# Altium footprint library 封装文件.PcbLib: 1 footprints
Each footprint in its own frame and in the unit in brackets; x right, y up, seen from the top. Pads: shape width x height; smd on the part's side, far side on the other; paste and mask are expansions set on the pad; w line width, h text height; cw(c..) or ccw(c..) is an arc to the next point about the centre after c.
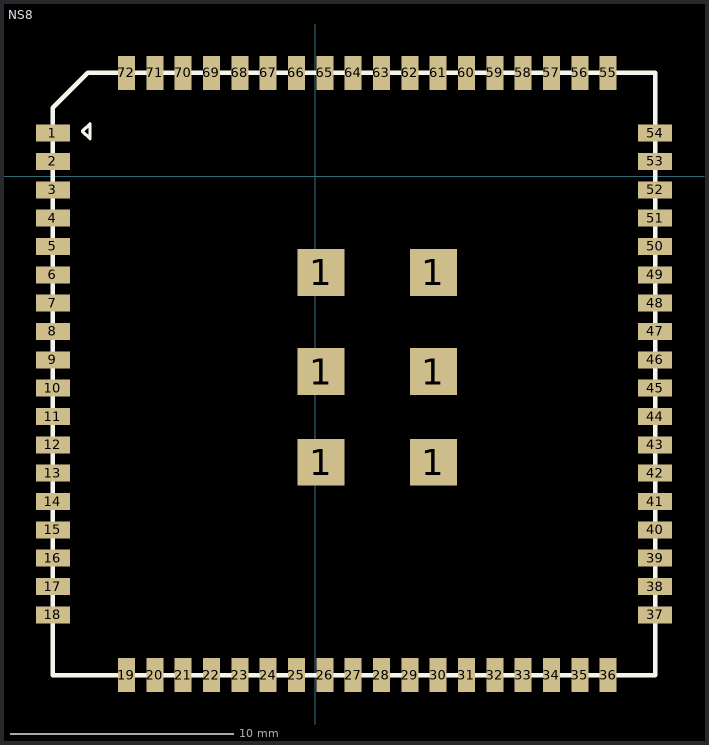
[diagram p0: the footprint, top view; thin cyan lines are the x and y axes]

## NS8 [mil]
pads (78):
  rect 60x30 smd: 1(-463.27,75.98) 2(-463.27,25.98) 3(-463.27,-24.02) 4(-463.27,-74.02) 5(-463.27,-124.02) 6(-463.27,-174.02) 7(-463.27,-224.02) 8(-463.27,-274.02) 9(-463.27,-324.02) 10(-463.27,-374.02) 11(-463.27,-424.02) 12(-463.27,-474.02) 13(-463.27,-524.02) 14(-463.27,-574.02) 15(-463.27,-624.02) 16(-463.27,-674.02) 17(-463.27,-724.02) 18(-463.27,-774.02) 37(599.72,-774.02) 38(599.72,-724.02) 39(599.72,-674.02) 40(599.72,-624.02) 41(599.72,-574.02) 42(599.72,-524.02) 43(599.72,-474.02) 44(599.72,-424.02) 45(599.72,-374.02) 46(599.72,-324.02) 47(599.72,-274.02) 48(599.72,-224.02) 49(599.72,-174.02) 50(599.72,-124.02) 51(599.72,-74.02) 52(599.72,-24.02) 53(599.72,25.98) 54(599.72,75.98)
  rect 82.68x82.68 smd: 1(10.17,-504.69) 1(10.17,-344.69) 1(10.17,-169.69) 1(208.32,-504.69) 1(208.32,-344.69) 1(208.32,-169.69)
  rect 30x60 smd: 19(-333.35,-880.51) 20(-283.35,-880.51) 21(-233.35,-880.51) 22(-183.35,-880.51) 23(-133.35,-880.51) 24(-83.35,-880.51) 25(-33.35,-880.51) 26(16.65,-880.51) 27(66.65,-880.51) 28(116.65,-880.51) 29(166.65,-880.51) 30(216.65,-880.51) 31(266.65,-880.51) 32(316.65,-880.51) 33(366.65,-880.51) 34(416.65,-880.51) 35(466.65,-880.51) 36(516.65,-880.51) 55(516.65,182.48) 56(466.65,182.48) 57(416.65,182.48) 58(366.65,182.48) 59(316.65,182.48) 60(266.65,182.48) 61(216.65,182.48) 62(166.65,182.48) 63(116.65,182.48) 64(66.65,182.48) 65(16.65,182.48) 66(-33.35,182.48) 67(-83.35,182.48) 68(-133.35,182.48) 69(-183.35,182.48) 70(-233.35,182.48) 71(-283.35,182.48) 72(-333.35,182.48)
Top Overlay:
  lines w3.94: -410.91,79.33 -410.91,79.33
  lines w5.91: -410.91,79.33 -397.52,65.94 -397.52,92.72 -410.91,79.33
  lines w7.87: -463.27,-880.51 599.72,-880.51 599.72,182.48 -401.85,182.48 -463.27,121.06 -463.27,-880.51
